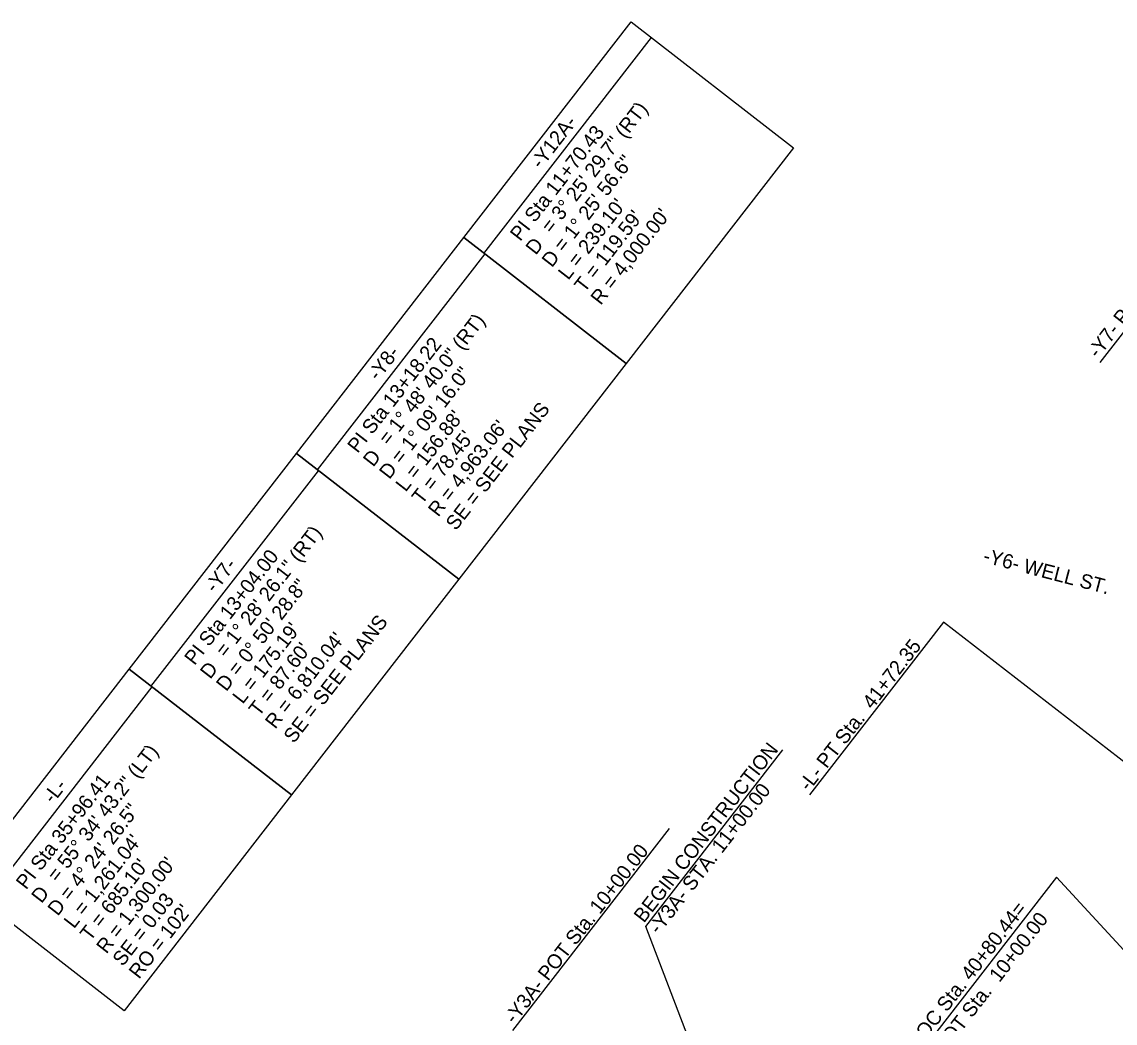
# Model space of a CAD drawing. Extents: x 2010838 to 2015151, y 441905 to 447792.
# Drawn here: x 2013578 to 2014110, y 445400 to 445887 of the extents above; entities that cross this region are included whole.
import ezdxf

# ---------------------------------------------------------------- set-up
doc = ezdxf.new("R2010")
doc.units = 0
for name, color, linetype in [('C-CURB STOPS', 7, 'Continuous'), ('C-Grave Plots', 7, 'Continuous'), ('CLRD', 7, 'Continuous'), ('DEED', 7, 'Continuous'), ('Default_10ft_LIDAR_Contou', 7, 'Continuous'), ('Default_Parcels', 7, 'Continuous'), ('HATCH', 7, 'Continuous'), ('S-Existing Minor', 7, 'Continuous'), ('S-overhead electric', 7, 'Continuous'), ('TEXT-LG', 7, 'Continuous'), ('TEXT-MED', 7, 'Continuous')]:
    doc.layers.add(name, color=color, linetype=linetype)

msp = doc.modelspace()

# ---------------------------------------------------------------- linework, layer by layer
at = {"layer": 'C-CURB STOPS'}
msp.add_arc((2013223.9, 446217.91), 1292, 312.84627, 322.2051, dxfattribs=at)
msp.add_arc((2013223.9, 446217.91), 1292, 312.84627, 322.2051, dxfattribs=at)
at = {"layer": 'CLRD'}
msp.add_arc((2013223.9, 446217.91), 1300, 266.62643, 322.2051, dxfattribs=at)
at = {"layer": 'DEED'}
msp.add_arc((2013223.9, 446217.91), 1292, 312.84627, 322.2051, dxfattribs=at)
at = {"layer": 'Default_10ft_LIDAR_Contou'}
for p, q in [((2014174.25, 445813.79), (2014102.71, 445721.55)), ((2014026.73, 445595.29), (2013961.5, 445511.19)), ((2014249.99, 445422.14), (2014026.73, 445595.29)), ((2013817.29, 445396.57), (2013893.45, 445494.77)), ((2014081.56, 445471.13), (2014005.12, 445372.57)), ((2014191.6, 445351.95), (2014081.56, 445471.13))]:
    msp.add_line(p, q, dxfattribs=at)
at = {"layer": 'Default_Parcels'}
for p, q in [((2013803.18, 445774.66), (2013884.59, 445879.63)), ((2013722.27, 445669.38), (2013803.68, 445774.35)), ((2013641.22, 445563.92), (2013722.63, 445668.89)), ((2013560.72, 445459.17), (2013641.78, 445563.7))]:
    msp.add_line(p, q, dxfattribs=at)
for points in [[(2013793.42, 445782.3), (2013874.83, 445887.27), (2013953.75, 445826.06), (2013872.35, 445721.09)], [(2013712.01, 445677.33), (2013793.42, 445782.3), (2013872.35, 445721.09), (2013790.94, 445616.12)], [(2013630.6, 445572.36), (2013712.01, 445677.33), (2013790.94, 445616.12), (2013709.53, 445511.15)], [(2013549.2, 445467.39), (2013630.6, 445572.36), (2013709.53, 445511.15), (2013628.12, 445406.18)]]:
    msp.add_lwpolyline(points, close=True, dxfattribs=at)
at = {"layer": 'HATCH'}
for radius, start in [(1279.25, 293.04012), (1291.25, 312.84627)]:
    msp.add_arc((2013223.9, 446217.91), radius, start, 322.2051, dxfattribs=at)
at = {"layer": 'S-Existing Minor'}
for p, q in [((2013881.87, 445447.14), (2013948.52, 445533.09)), ((2013936.5, 445304.58), (2013881.87, 445447.14))]:
    msp.add_line(p, q, dxfattribs=at)
at = {"layer": 'S-overhead electric'}
msp.add_arc((2013223.9, 446217.91), 1265.25, 313.26766, 322.2051, dxfattribs=at)
at = {"layer": 'TEXT-LG'}
for radius in [1253.75, 1258.75]:
    msp.add_arc((2013223.9, 446217.91), radius, 313.26766, 322.2051, dxfattribs=at)
at = {"layer": 'TEXT-MED'}
msp.add_arc((2013223.9, 446217.91), 1263.25, 313.26766, 322.2051, dxfattribs=at)

# ---------------------------------------------------------------- texts
at = {"layer": 'C-Grave Plots'}
for s, rotation, p in [('-Y6- WELL ST.', 345.4833, (2014045.52, 445624.5)), ('BEGIN CONSTRUCTION', 52.1339, (2013880.97, 445448.55)), ('-Y3A- STA. 11+00.00', 52.1339, (2013888.21, 445442.92))]:
    msp.add_text(s, height=7, rotation=rotation, dxfattribs=at).set_placement(p)
at = {"layer": 'Default_10ft_LIDAR_Contou'}
for s, p in [('-Y7- POT Sta.  10+00.00', (2014101.78, 445723.21)), ('-L- PT Sta.  41+72.35', (2013961.23, 445512.57)), ('-Y3A- POT Sta. 10+00.00', (2013818.07, 445399.33)), ('-L- POC Sta. 40+80.44=', (2014005.65, 445376.01)), ('-Y4- POT Sta.  10+00.00', (2014014.64, 445369.04))]:
    msp.add_text(s, height=7, rotation=52.2051, dxfattribs=at).set_placement(p)
at = {"layer": 'Default_Parcels'}
for s, p in [('= 3%%d 25\' 29.7" (RT)', (2013835.92, 445783.87)), ('PI Sta 11+70.43', (2013820.81, 445780.15)), ('-Y12A-', (2013830.83, 445815.29)), ('D = 1%%d 25\' 56.6"', (2013836.23, 445767.4)), ("L = 239.10'", (2013844.17, 445761.28)), ("T = 119.59'", (2013852.09, 445755.17)), ("R = 4,000.00'", (2013859.99, 445749.07)), ('D', (2013828.38, 445773.46)), ('= 1%%d 48\' 40.0" (RT)', (2013756.82, 445680.82)), ('PI Sta 13+18.22', (2013741.72, 445677.07)), ('-Y8-', (2013751.66, 445712.25)), ('D = 1%%d 09\' 16.0"', (2013757.16, 445664.34)), ('SE = SEE PLANS', (2013789.52, 445639.4)), ("L = 156.88'", (2013765.11, 445658.23)), ("R = 4,963.06'", (2013780.94, 445646.05)), ("T = 78.45'", (2013773.04, 445652.13)), ('D', (2013749.33, 445670.36)), ('= 1%%d 28\' 26.1" (RT)', (2013677.51, 445577.62)), ('PI Sta 13+04.00', (2013662.41, 445573.86)), ('-Y7-', (2013672.36, 445609.04)), ('D = 0%%d 50\' 28.8"', (2013677.86, 445561.15)), ('SE = SEE PLANS', (2013710.69, 445535.88)), ("L = 175.19'", (2013685.84, 445555.02)), ("R = 6,810.04'", (2013701.68, 445542.87)), ("T = 87.60'", (2013693.77, 445548.94)), ('D', (2013670.06, 445567.14)), ('= 55%%d 34\' 43.2" (LT)', (2013595.66, 445468.36)), ('PI Sta 35+96.41', (2013580.52, 445464.7)), ('-L-', (2013593.59, 445506.53)), ('D = 4%%d 24\' 26.5"', (2013595.91, 445451.9)), ("L = 1,261.04'", (2013603.8, 445445.77)), ("T = 685.10'", (2013611.7, 445439.64)), ("R = 1,300.00'", (2013619.6, 445433.51)), ('D', (2013588, 445458.05)), ('SE = 0.03', (2013627.5, 445427.38)), ("RO = 102'", (2013635.4, 445421.24))]:
    msp.add_text(s, height=7, rotation=52.2051, dxfattribs=at).set_placement(p)

doc.saveas('drawing.dxf')
